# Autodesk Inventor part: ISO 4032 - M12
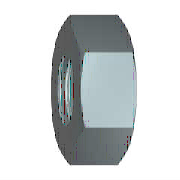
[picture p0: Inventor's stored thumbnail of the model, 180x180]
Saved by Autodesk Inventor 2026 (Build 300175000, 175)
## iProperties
Created: 2025-01
Part Number: ISO 4032 - M12
Material: Acier inoxydable 440C
Description: Ecrous hexagonaux - Style 1 - Produits de classes A et B
Document SubType Name: Modeling
Standard: ISO 4032
Designer: thierry.jost
Standards Organization: AFNOR
Language: fr-FR
Size Designation: M12
Categories: <MemberInstance><Categories><Category DisplayName="Visserie" InternalName="e4da775c-781d-43d5-af7c-5136215cf5a6" Mnemonic="FSTN"><Category DisplayName="Ecrous"
Density: 7.75 g/cm^3
Appearance: Semi-poli
IsCustomPart: 0
Author: thierry.jost
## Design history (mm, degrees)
workaxis "Work Axis1"
workplane "Work Plane1"
sketch "Esquisse1"
  geometry: L1 (-10.392, 0)-(-5.196, 9); L2 (-5.196, 9)-(5.196, 9); L3 (5.196, 9)-(10.392, 0); L4 (10.392, 0)-(5.196, -9); L5 (5.196, -9)-(-5.196, -9); L6 (-5.196, -9)-(-10.392, 0); 2 further points
  constraints: 12 end point, 1 coincident, 1 horizontal, 11 other
  dimensions: "d0" = 20.78461 distance of L3.end L1.start (= 1.1547 x SW)
extrude "Corps" new body sketch "Esquisse1" distance "d1" = 10.8 (= KOH); taper "d2" = 0 deg
revolve "Chanfrein1" stored, may be unused: angle "d7" = 90 deg
sketch "Esquisse3"
  geometry: A1 r 9 centre (0, 0) between (-4.5, -7.794) and (4.5, -7.794) reference; 1 further point
  constraints: 1 coincident
hole "Filetage" sketch "Esquisse3" diameter "d25" = 10.106; stored, may be unused: countersink angle "d29" = 82 deg, drill point angle "d31" = 118 deg; dims "d26" = 6, "d27" = 4, "d28" = 2, "d30" = 8
body "Solid1"
chamfer "Chanfrein2" distance "d8" = 0.94722 (= -0.5 x GD1 + 0.5 x NND); stored, may be unused: angle "d9" = 30 deg, second distance "d40" = 0.94722 (= -0.5 x GD1 + 0.5 x NND)
chamfer "Chanfrein3" distance "d10" = 0.94722 (= -0.5 x GD1 + 0.5 x NND); stored, may be unused: angle "d11" = 30 deg, second distance "d41" = 0.94722 (= -0.5 x GD1 + 0.5 x NND)
sketch "Esquisse2"
  geometry: L1 (0, 5.196)-(0, 10.392) reference; L2 (0, 10.392)-(10.8, 10.392) reference; L3 (10.8, 5.196)-(10.8, 10.392) reference; L4 (-2.16, 0)-(12.96, 0) reference; L5 (0.804, 10.392)-(0, 9); L6 (9.996, 10.392)-(10.8, 9)
  constraints: 4 end point, 4 point on line
  dimensions: "d3" = 30 deg angle of L1 L5 (= ANG1); "d4" = 30 deg angle of L3 L6 (= ANG2); "d5" = 18 diameter of L5.end L4 (= SW0); "d6" = 18 diameter of L6.end L4 (= SW01)
other parameters: "ANG1" = 30 deg [user parameter; used in 1 equation term], "ANG2" = 30 deg [user parameter; used in 1 equation term], "NND" = 12 [user parameter; used in 4 equation terms], "KOH" = 10.8 [user parameter; used in 1 equation term], "SW" = 18 [user parameter; used in 2 equation terms], "SW0" = 18 [user parameter; used in 2 equation terms], "SW01" = 18 (= SW0) [user parameter; used in 1 equation term], "GD1" = 10.10557 (computed from THREADDIA, PTC, TOA) [user parameter; used in 4 equation terms], "d13" = 0, "d14" = 0, "d39" = 0, "d42" = 0, "GUL" = 0.94722 (= 0.541266 x PTC) [user parameter], "TPU" = 5.71429 (computed from PTC) [user parameter], "THREADDIA" = 12 [user parameter; used in 1 equation term], "TOA" = 30 deg [user parameter; used in 1 equation term], "PTC" = 1.75 [user parameter; used in 4 equation terms], "E0" = 20.79 (= 1.155 x SW) [user parameter], "GAL" = 0.94722 (= 0.541266 x PTC) [user parameter]
